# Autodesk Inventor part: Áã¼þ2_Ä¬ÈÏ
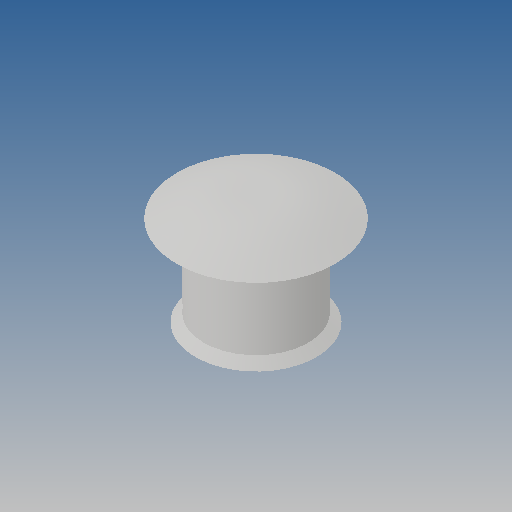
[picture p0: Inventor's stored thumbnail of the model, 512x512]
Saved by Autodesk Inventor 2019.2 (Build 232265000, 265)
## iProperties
Created: 2010-06
Part Number: Áã¼þ2_Ä¬ÈÏ
Material: Ogólny
Document SubType Name: Modeling
Designer: CADENGINEERING4
Density: 1 g/cm^3
Appearance: Domyślna
Author: CADENGINEERING4
Revision Number: ÈÎºÎ
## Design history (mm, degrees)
feature "NONE"
node "Bryła1"
